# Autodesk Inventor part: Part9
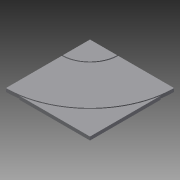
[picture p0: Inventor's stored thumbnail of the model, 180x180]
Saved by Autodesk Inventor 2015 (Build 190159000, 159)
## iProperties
Created: 2015-04
Part Number: Part9
Material: Generic
Document SubType Name: Modeling
Designer: TREINA5
Density: 1 g/cm^3
Appearance: Default
Mass: 128083 g
Surface Area: 49379.4 cm^2
Volume: 128083 cm^3
Author: TREINA5
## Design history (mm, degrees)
sketch "Sketch1"
  geometry: L1 (3000, 2999.966)-(3000, 3980.132); L2 (3234.742, 2999.966)-(4480, 2999.966); L3 (3000, 4000.034)-(3000, 4479.983); L4 (3000, 4479.983)-(3479.966, 4479.966); L5 (4480, 4245.054)-(4480, 2999.966); L6 (3000, 2999.966)-(3000, 3980.132); L7 (3000, 3000)-(3000, 3980.132); L8 (3000, 4000.034)-(3000, 4480); L9 (3499.869, 4480.034)-(4480, 4480); A1 r 1490.034 centre (2990, 4490) between (3000, 3000) and (4480, 4480); A2 r 1510 centre (2990, 4490) between (3234.742, 2999.966) and (4480, 4245.054); A3 r 509.966 centre (2990, 4490) between (3000, 3980.132) and (3499.869, 4480.034); A4 r 490.068 centre (2990, 4490) between (3000, 4000.034) and (3479.967, 4480.034); A5 r 508.316 centre (2990.032, 4488.35) between (3000, 3980.132) and (3000, 3980.132); A6 r 517.418 centre (2982.55, 4490.146) between (3499.869, 4480.034) and (3499.869, 4480.034); A7 r 509.966 centre (2990, 4490) between (3000, 3980.132) and (3499.869, 4480.034); A8 r 120.916 centre (4600.914, 4479.188) between (4480, 4480) and (4480, 4480); 2 further points
  constraints: 20 point on circle, 18 end point, 8 centre point, 4 tangent, 2 collinear, 2 point on line, 1 parallel, 1 other
extrude "Extrusion1" new body sketch "Sketch1" distance "d0" = 60; taper "d1" = 0 deg
extrude "Extrusion2" new body sketch "Sketch1" distance "d2" = 60; taper "d3" = 0 deg
extrude "Extrusion3" new body sketch "Sketch1" distance "d4" = 60; taper "d5" = 0 deg
body "Solid1"
body "Solid2"
body "Solid3"
